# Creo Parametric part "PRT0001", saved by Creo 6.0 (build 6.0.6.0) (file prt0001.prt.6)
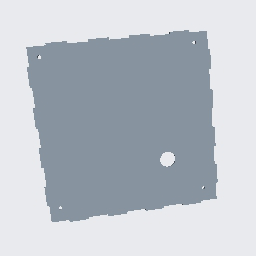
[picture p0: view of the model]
Units: Inch lbm Second (Pro/E Default); INCH, POUND, SECS

Created from: INLBS_PART_SOLID.PRT

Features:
  1. datum plane "RIGHT"
  2. datum plane "TOP"
  3. datum plane "FRONT"
  4. coordinate system
  5. sketch "Sketch 1"
  6. extrusion "Extrude 1"
  7. sketch "Sketch 2"
  8. extruded cut "Extrude 2"
  9. sketch "Sketch 3"
  10. extruded cut "Extrude 3"
  11. sketch "Sketch 4"
  12. extruded cut "Extrude 4"

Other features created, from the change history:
  extrusion "Extrude 2" (2 times)
  mirror "Mirror 1"

Surfaces: 70 plane, 5 cylinder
